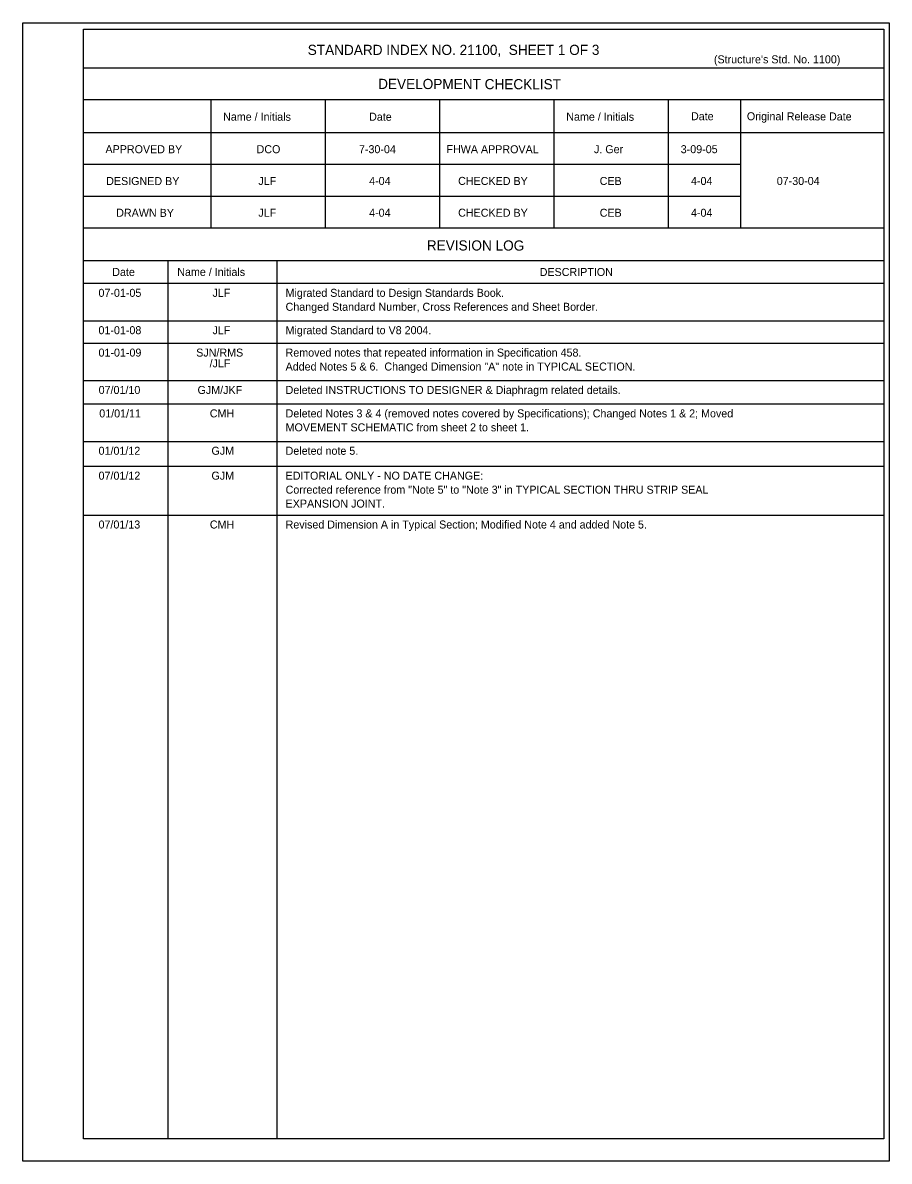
# Model space of a CAD drawing. Extents: x 0 to 9.02, y -1.12 to 4.98.
# Drawn here: x 6.289 to 9.016, y -0.082 to 3.502 of the extents above; entities that cross this region are included whole.
import ezdxf

# ---------------------------------------------------------------- set-up
doc = ezdxf.new("R2010")
doc.units = 0
for name, color, linetype in [('Border', 7, 'Continuous'), ('Dimension', 7, 'Continuous'), ('PlotBorder_dp', 7, 'Continuous'), ('TextStructures', 7, 'Continuous')]:
    doc.layers.add(name, color=color, linetype=linetype)

msp = doc.modelspace()

# ---------------------------------------------------------------- linework, layer by layer
at = {"layer": 'Border'}
for p, q in [((8.9985, 3.3588), (6.4802, 3.3588)), ((8.9985, 3.2588), (6.4802, 3.2588)), ((6.8802, 3.2588), (6.8802, 2.8554)), ((7.2402, 3.2588), (7.2402, 2.8554)), ((7.6002, 3.2588), (7.6002, 2.8554)), ((7.9602, 3.2588), (7.9602, 2.8554)), ((8.3202, 3.2588), (8.3202, 2.8554)), ((8.547, 3.2588), (8.547, 2.8554)), ((8.9985, 3.1554), (6.4802, 3.1554)), ((8.547, 3.0554), (6.4802, 3.0554)), ((8.547, 2.9554), (6.4802, 2.9554)), ((8.9985, 2.8554), (6.4802, 2.8554)), ((8.9985, 2.7519), (6.4802, 2.7519)), ((6.7452, 2.7519), (6.7452, -0.0114)), ((7.088, 2.7519), (7.088, -0.0114)), ((8.9985, 2.6814), (6.4802, 2.6814))]:
    msp.add_line(p, q, dxfattribs=at)
msp.add_lwpolyline([(6.4802, 3.4814), (8.9985, 3.4814), (8.9985, -0.0114), (6.4802, -0.0114)], close=True, dxfattribs=at)
at = {"layer": 'Dimension'}
for p, q in [((6.4802, 2.5637), (8.9985, 2.5637)), ((6.4802, 2.4933), (8.9985, 2.4933)), ((6.4802, 2.3756), (8.9985, 2.3756)), ((6.4802, 2.3019), (8.9985, 2.3019)), ((6.4802, 2.1842), (8.9986, 2.1842)), ((6.4802, 2.1058), (8.9986, 2.1058)), ((6.4802, 1.9521), (8.9986, 1.9521))]:
    msp.add_line(p, q, dxfattribs=at)
at = {"layer": 'PlotBorder_dp'}
msp.add_line((6.2889, -0.0816), (6.2889, -0.0816), dxfattribs=at)
msp.add_lwpolyline([(6.2889, 3.5017), (9.0155, 3.5017), (9.0155, -0.0816), (6.2889, -0.0816)], close=True, dxfattribs=at)

# ---------------------------------------------------------------- texts
at = {"layer": 'TextStructures'}
for s, height, p in [('STANDARD INDEX NO. 21100,  SHEET 1 OF 3', 0.032, (7.1856, 3.4004)), ("(Structure's Std. No. 1100)", 0.0252, (8.4639, 3.374)), ('DCO', 0.0252, (7.0247, 3.0912)), ('7-30-04', 0.0252, (7.3468, 3.0912)), ('J. Ger', 0.0252, (8.0864, 3.0912)), ('3-09-05', 0.0252, (8.3594, 3.0912)), ('JLF', 0.0252, (7.0301, 2.9912)), ('4-04', 0.0252, (7.3788, 2.9912)), ('CEB', 0.0252, (8.1044, 2.9912)), ('4-04', 0.0252, (8.3917, 2.9912)), ('07-30-04', 0.0252, (8.6616, 2.9912)), ('JLF', 0.0252, (7.0301, 2.8912)), ('4-04', 0.0252, (7.3788, 2.8912)), ('CEB', 0.0252, (8.1044, 2.8912)), ('4-04', 0.0252, (8.3917, 2.8912)), ('DESCRIPTION', 0.0252, (7.9156, 2.7047)), ('07-01-05', 0.0252, (6.5271, 2.6391)), ('JLF', 0.0252, (6.886, 2.6391)), ('Migrated Standard to Design Standards Book.', 0.0252, (7.1159, 2.6391)), ('Changed Standard Number, Cross References and Sheet Border.', 0.0252, (7.1159, 2.5952)), ('01-01-08', 0.0252, (6.5271, 2.5215)), ('JLF', 0.0252, (6.886, 2.5215)), ('Migrated Standard to V8 2004.', 0.0252, (7.1159, 2.5215)), ('01-01-09', 0.0252, (6.5272, 2.451)), ('SJN/RMS', 0.0252, (6.8346, 2.451)), ('Removed notes that repeated information in Specification 458.', 0.0252, (7.1159, 2.451)), ('/JLF', 0.0252, (6.8768, 2.4172)), ('Added Notes 5 & 6.  Changed Dimension "A" note in TYPICAL SECTION.', 0.0252, (7.1159, 2.4071)), ('07/01/10', 0.0252, (6.5276, 2.3334)), ('GJM/JKF', 0.0252, (6.8389, 2.3334)), ('Deleted INSTRUCTIONS TO DESIGNER & Diaphragm related details.', 0.0252, (7.116, 2.3334)), ('01/01/11', 0.0252, (6.5296, 2.2596)), ('CMH', 0.0252, (6.8775, 2.2596)), ('Deleted Notes 3 & 4 (removed notes covered by Specifications); Changed Notes 1 & 2; Moved', 0.0252, (7.116, 2.2596)), ('MOVEMENT SCHEMATIC from sheet 2 to sheet 1.', 0.0252, (7.116, 2.2157)), ('01/01/12', 0.0252, (6.5274, 2.142)), ('GJM', 0.0252, (6.8827, 2.142)), ('Deleted note 5.', 0.0252, (7.116, 2.142)), ('07/01/12', 0.0252, (6.5274, 2.0636)), ('GJM', 0.0252, (6.8827, 2.0636)), ('EDITORIAL ONLY - NO DATE CHANGE:', 0.0252, (7.116, 2.0636)), ('Corrected reference from "Note 5" to "Note 3" in TYPICAL SECTION THRU STRIP SEAL ', 0.0252, (7.116, 2.0196)), ('EXPANSION JOINT.', 0.0252, (7.116, 1.9757)), ('07/01/13', 0.0252, (6.5273, 1.9099)), ('CMH', 0.0252, (6.8776, 1.9099)), ('Revised Dimension A in Typical Section; Modified Note 4 and added Note 5.', 0.0252, (7.116, 1.9099))]:
    msp.add_text(s, height=height, dxfattribs=at).set_placement(p)
for s, height, p in [('DEVELOPMENT CHECKLIST', 0.032, (7.4071, 3.2934)), ('Name / Initials', 0.0252, (6.9192, 3.1937)), ('Date', 0.0252, (7.3786, 3.1935)), ('Name / Initials', 0.0252, (7.9992, 3.1937)), ('Date', 0.0252, (8.3917, 3.195)), ('Original Release Date', 0.0252, (8.5675, 3.1949)), ('APPROVED BY', 0.0252, (6.5491, 3.0914)), ('FHWA APPROVAL', 0.0252, (7.6221, 3.0914)), ('DESIGNED BY', 0.0252, (6.5513, 2.9912)), ('CHECKED BY', 0.0252, (7.6589, 2.9914)), ('DRAWN BY', 0.0252, (6.5829, 2.8912)), ('CHECKED BY', 0.0252, (7.6589, 2.8914)), ('REVISION LOG', 0.032, (7.5603, 2.7852)), ('Date', 0.0252, (6.5705, 2.7048)), ('Name / Initials', 0.0252, (6.775, 2.7051))]:
    msp.add_text(s, height=height, rotation=359.8756, dxfattribs=at).set_placement(p)

doc.saveas('drawing.dxf')
